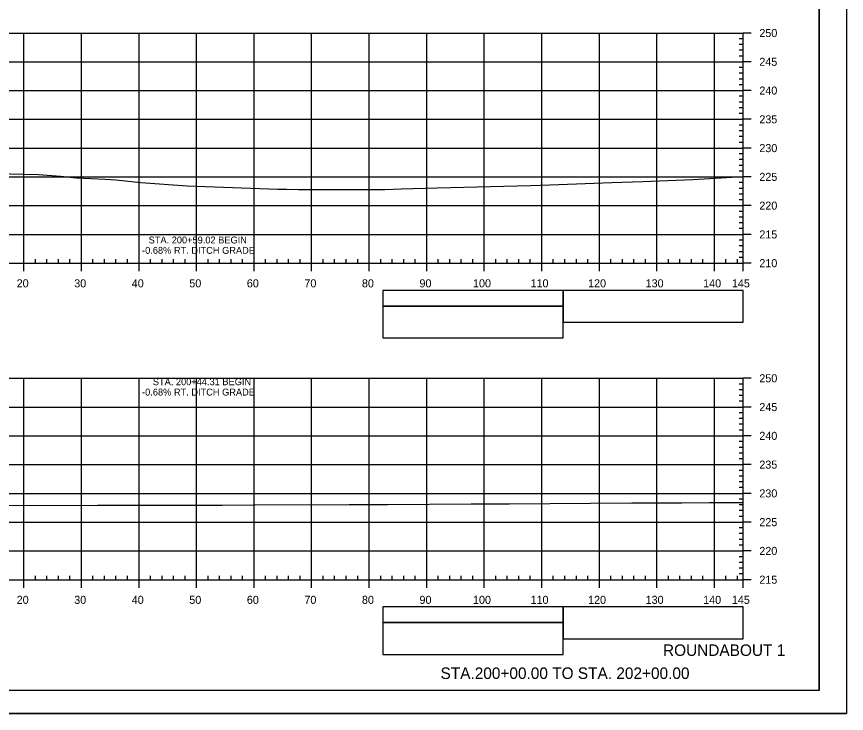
# Model space of a CAD drawing. Extents: x 1386544 to 1388153, y 379785 to 390999.
# Drawn here: x 1387399.1 to 1387543.3, y 380478.3 to 380599.4 of the extents above; entities that cross this region are included whole.
import ezdxf

# ---------------------------------------------------------------- set-up
doc = ezdxf.new("R2010")
doc.units = 0
for name, color, linetype in [('R_Axis', 7, 'Continuous'), ('R_Axis Annot', 7, 'Continuous'), ('R_Border', 7, 'Continuous'), ('R_Draft', 7, 'Continuous'), ('R_Exist Surface', 7, 'Continuous'), ('R_Fin Surface', 7, 'Continuous'), ('R_Grid', 7, 'Continuous'), ('R_No Plot', 7, 'Continuous'), ('R_Striping', 7, 'Continuous'), ('R_Xsect Elev', 7, 'Continuous')]:
    doc.layers.add(name, color=color, linetype=linetype)

msp = doc.modelspace()

# ---------------------------------------------------------------- linework, layer by layer
at = {"layer": 'R_Axis'}
for p, q in [((1387525.41, 380595.56), (1387524.71, 380595.56)), ((1387525.41, 380556.56), (1387525.41, 380596.56)), ((1387526.81, 380596.56), (1387525.41, 380596.56)), ((1387525.41, 380594.56), (1387524.71, 380594.56)), ((1387525.41, 380593.56), (1387524.71, 380593.56)), ((1387525.41, 380592.56), (1387524.71, 380592.56)), ((1387526.81, 380591.56), (1387525.41, 380591.56)), ((1387525.41, 380590.56), (1387524.71, 380590.56)), ((1387525.41, 380589.56), (1387524.71, 380589.56)), ((1387525.41, 380588.56), (1387524.71, 380588.56)), ((1387525.41, 380587.56), (1387524.71, 380587.56)), ((1387526.81, 380586.56), (1387525.41, 380586.56)), ((1387525.41, 380585.56), (1387524.71, 380585.56)), ((1387525.41, 380584.56), (1387524.71, 380584.56)), ((1387525.41, 380583.56), (1387524.71, 380583.56)), ((1387525.41, 380582.56), (1387524.71, 380582.56)), ((1387526.81, 380581.56), (1387525.41, 380581.56)), ((1387525.41, 380580.56), (1387524.71, 380580.56)), ((1387525.41, 380579.56), (1387524.71, 380579.56)), ((1387525.41, 380578.56), (1387524.71, 380578.56)), ((1387525.41, 380577.56), (1387524.71, 380577.56)), ((1387526.81, 380576.56), (1387525.41, 380576.56)), ((1387525.41, 380575.56), (1387524.71, 380575.56)), ((1387525.41, 380574.56), (1387524.71, 380574.56)), ((1387525.41, 380573.56), (1387524.71, 380573.56)), ((1387525.41, 380572.56), (1387524.71, 380572.56)), ((1387526.81, 380571.56), (1387525.41, 380571.56)), ((1387525.41, 380570.56), (1387524.71, 380570.56)), ((1387525.41, 380569.56), (1387524.71, 380569.56)), ((1387525.41, 380568.56), (1387524.71, 380568.56)), ((1387525.41, 380567.56), (1387524.71, 380567.56)), ((1387526.81, 380566.56), (1387525.41, 380566.56)), ((1387525.41, 380565.56), (1387524.71, 380565.56)), ((1387525.41, 380564.56), (1387524.71, 380564.56)), ((1387525.41, 380563.56), (1387524.71, 380563.56)), ((1387525.41, 380562.56), (1387524.71, 380562.56)), ((1387525.41, 380560.56), (1387524.71, 380560.56)), ((1387526.81, 380561.56), (1387525.41, 380561.56)), ((1387525.41, 380559.56), (1387524.71, 380559.56)), ((1387525.41, 380558.56), (1387524.71, 380558.56)), ((1387235.41, 380556.56), (1387525.41, 380556.56)), ((1387400.41, 380555.16), (1387400.41, 380556.56)), ((1387402.41, 380556.56), (1387402.41, 380557.26)), ((1387404.41, 380556.56), (1387404.41, 380557.26)), ((1387406.41, 380556.56), (1387406.41, 380557.26)), ((1387408.41, 380556.56), (1387408.41, 380557.26)), ((1387410.41, 380555.16), (1387410.41, 380556.56)), ((1387412.41, 380556.56), (1387412.41, 380557.26)), ((1387414.41, 380556.56), (1387414.41, 380557.26)), ((1387416.41, 380556.56), (1387416.41, 380557.26)), ((1387418.41, 380556.56), (1387418.41, 380557.26)), ((1387420.41, 380555.16), (1387420.41, 380556.56)), ((1387422.41, 380556.56), (1387422.41, 380557.26)), ((1387424.41, 380556.56), (1387424.41, 380557.26)), ((1387426.41, 380556.56), (1387426.41, 380557.26)), ((1387428.41, 380556.56), (1387428.41, 380557.26)), ((1387430.41, 380555.16), (1387430.41, 380556.56)), ((1387432.41, 380556.56), (1387432.41, 380557.26)), ((1387434.41, 380556.56), (1387434.41, 380557.26)), ((1387436.41, 380556.56), (1387436.41, 380557.26)), ((1387438.41, 380556.56), (1387438.41, 380557.26)), ((1387440.41, 380555.16), (1387440.41, 380556.56)), ((1387442.41, 380556.56), (1387442.41, 380557.26)), ((1387444.41, 380556.56), (1387444.41, 380557.26)), ((1387446.41, 380556.56), (1387446.41, 380557.26)), ((1387448.41, 380556.56), (1387448.41, 380557.26)), ((1387450.41, 380555.16), (1387450.41, 380556.56)), ((1387452.41, 380556.56), (1387452.41, 380557.26)), ((1387454.41, 380556.56), (1387454.41, 380557.26)), ((1387456.41, 380556.56), (1387456.41, 380557.26)), ((1387458.41, 380556.56), (1387458.41, 380557.26)), ((1387460.41, 380555.16), (1387460.41, 380556.56)), ((1387462.41, 380556.56), (1387462.41, 380557.26)), ((1387464.41, 380556.56), (1387464.41, 380557.26)), ((1387466.41, 380556.56), (1387466.41, 380557.26)), ((1387468.41, 380556.56), (1387468.41, 380557.26)), ((1387470.41, 380555.16), (1387470.41, 380556.56)), ((1387472.41, 380556.56), (1387472.41, 380557.26)), ((1387474.41, 380556.56), (1387474.41, 380557.26)), ((1387476.41, 380556.56), (1387476.41, 380557.26)), ((1387478.41, 380556.56), (1387478.41, 380557.26)), ((1387480.41, 380555.16), (1387480.41, 380556.56)), ((1387482.41, 380556.56), (1387482.41, 380557.26)), ((1387484.41, 380556.56), (1387484.41, 380557.26)), ((1387486.41, 380556.56), (1387486.41, 380557.26)), ((1387488.41, 380556.56), (1387488.41, 380557.26)), ((1387490.41, 380555.16), (1387490.41, 380556.56)), ((1387492.41, 380556.56), (1387492.41, 380557.26)), ((1387494.41, 380556.56), (1387494.41, 380557.26)), ((1387496.41, 380556.56), (1387496.41, 380557.26)), ((1387498.41, 380556.56), (1387498.41, 380557.26)), ((1387500.41, 380555.16), (1387500.41, 380556.56)), ((1387502.41, 380556.56), (1387502.41, 380557.26)), ((1387504.41, 380556.56), (1387504.41, 380557.26)), ((1387506.41, 380556.56), (1387506.41, 380557.26)), ((1387508.41, 380556.56), (1387508.41, 380557.26)), ((1387510.41, 380555.16), (1387510.41, 380556.56)), ((1387512.41, 380556.56), (1387512.41, 380557.26)), ((1387514.41, 380556.56), (1387514.41, 380557.26)), ((1387516.41, 380556.56), (1387516.41, 380557.26)), ((1387518.41, 380556.56), (1387518.41, 380557.26)), ((1387520.41, 380555.16), (1387520.41, 380556.56)), ((1387522.41, 380556.56), (1387522.41, 380557.26)), ((1387524.41, 380556.56), (1387524.41, 380557.26)), ((1387525.41, 380557.56), (1387524.71, 380557.56)), ((1387525.41, 380555.16), (1387525.41, 380556.56)), ((1387526.81, 380556.56), (1387525.41, 380556.56)), ((1387525.41, 380501.56), (1387525.41, 380536.56)), ((1387526.81, 380536.56), (1387525.41, 380536.56)), ((1387525.41, 380535.56), (1387524.71, 380535.56)), ((1387525.41, 380534.56), (1387524.71, 380534.56)), ((1387525.41, 380533.56), (1387524.71, 380533.56)), ((1387525.41, 380532.56), (1387524.71, 380532.56)), ((1387525.41, 380530.56), (1387524.71, 380530.56)), ((1387526.81, 380531.56), (1387525.41, 380531.56)), ((1387525.41, 380529.56), (1387524.71, 380529.56)), ((1387525.41, 380528.56), (1387524.71, 380528.56)), ((1387525.41, 380527.56), (1387524.71, 380527.56)), ((1387526.81, 380526.56), (1387525.41, 380526.56)), ((1387525.41, 380525.56), (1387524.71, 380525.56)), ((1387525.41, 380524.56), (1387524.71, 380524.56)), ((1387525.41, 380523.56), (1387524.71, 380523.56)), ((1387525.41, 380522.56), (1387524.71, 380522.56)), ((1387525.41, 380520.56), (1387524.71, 380520.56)), ((1387526.81, 380521.56), (1387525.41, 380521.56)), ((1387525.41, 380519.56), (1387524.71, 380519.56)), ((1387525.41, 380518.56), (1387524.71, 380518.56)), ((1387525.41, 380517.56), (1387524.71, 380517.56)), ((1387526.81, 380516.56), (1387525.41, 380516.56)), ((1387525.41, 380515.56), (1387524.71, 380515.56)), ((1387525.41, 380514.56), (1387524.71, 380514.56)), ((1387525.41, 380513.56), (1387524.71, 380513.56)), ((1387525.41, 380512.56), (1387524.71, 380512.56)), ((1387526.81, 380511.56), (1387525.41, 380511.56)), ((1387525.41, 380510.56), (1387524.71, 380510.56)), ((1387525.41, 380509.56), (1387524.71, 380509.56)), ((1387525.41, 380508.56), (1387524.71, 380508.56)), ((1387525.41, 380507.56), (1387524.71, 380507.56)), ((1387526.81, 380506.56), (1387525.41, 380506.56)), ((1387525.41, 380505.56), (1387524.71, 380505.56)), ((1387525.41, 380504.56), (1387524.71, 380504.56)), ((1387525.41, 380503.56), (1387524.71, 380503.56)), ((1387235.41, 380501.56), (1387525.41, 380501.56)), ((1387400.41, 380500.16), (1387400.41, 380501.56)), ((1387402.41, 380501.56), (1387402.41, 380502.26)), ((1387404.41, 380501.56), (1387404.41, 380502.26)), ((1387406.41, 380501.56), (1387406.41, 380502.26)), ((1387408.41, 380501.56), (1387408.41, 380502.26)), ((1387410.41, 380500.16), (1387410.41, 380501.56)), ((1387412.41, 380501.56), (1387412.41, 380502.26)), ((1387414.41, 380501.56), (1387414.41, 380502.26)), ((1387416.41, 380501.56), (1387416.41, 380502.26)), ((1387418.41, 380501.56), (1387418.41, 380502.26)), ((1387420.41, 380500.16), (1387420.41, 380501.56)), ((1387422.41, 380501.56), (1387422.41, 380502.26)), ((1387424.41, 380501.56), (1387424.41, 380502.26)), ((1387426.41, 380501.56), (1387426.41, 380502.26)), ((1387428.41, 380501.56), (1387428.41, 380502.26)), ((1387430.41, 380500.16), (1387430.41, 380501.56)), ((1387432.41, 380501.56), (1387432.41, 380502.26)), ((1387434.41, 380501.56), (1387434.41, 380502.26)), ((1387436.41, 380501.56), (1387436.41, 380502.26)), ((1387438.41, 380501.56), (1387438.41, 380502.26)), ((1387440.41, 380500.16), (1387440.41, 380501.56)), ((1387442.41, 380501.56), (1387442.41, 380502.26)), ((1387444.41, 380501.56), (1387444.41, 380502.26)), ((1387446.41, 380501.56), (1387446.41, 380502.26)), ((1387448.41, 380501.56), (1387448.41, 380502.26)), ((1387450.41, 380500.16), (1387450.41, 380501.56)), ((1387452.41, 380501.56), (1387452.41, 380502.26)), ((1387454.41, 380501.56), (1387454.41, 380502.26)), ((1387456.41, 380501.56), (1387456.41, 380502.26)), ((1387458.41, 380501.56), (1387458.41, 380502.26)), ((1387460.41, 380500.16), (1387460.41, 380501.56)), ((1387462.41, 380501.56), (1387462.41, 380502.26)), ((1387464.41, 380501.56), (1387464.41, 380502.26)), ((1387466.41, 380501.56), (1387466.41, 380502.26)), ((1387468.41, 380501.56), (1387468.41, 380502.26)), ((1387470.41, 380500.16), (1387470.41, 380501.56)), ((1387472.41, 380501.56), (1387472.41, 380502.26)), ((1387474.41, 380501.56), (1387474.41, 380502.26)), ((1387476.41, 380501.56), (1387476.41, 380502.26)), ((1387478.41, 380501.56), (1387478.41, 380502.26)), ((1387480.41, 380500.16), (1387480.41, 380501.56)), ((1387482.41, 380501.56), (1387482.41, 380502.26)), ((1387484.41, 380501.56), (1387484.41, 380502.26)), ((1387486.41, 380501.56), (1387486.41, 380502.26)), ((1387488.41, 380501.56), (1387488.41, 380502.26)), ((1387490.41, 380500.16), (1387490.41, 380501.56)), ((1387492.41, 380501.56), (1387492.41, 380502.26)), ((1387494.41, 380501.56), (1387494.41, 380502.26)), ((1387496.41, 380501.56), (1387496.41, 380502.26)), ((1387498.41, 380501.56), (1387498.41, 380502.26)), ((1387500.41, 380500.16), (1387500.41, 380501.56)), ((1387502.41, 380501.56), (1387502.41, 380502.26)), ((1387504.41, 380501.56), (1387504.41, 380502.26)), ((1387506.41, 380501.56), (1387506.41, 380502.26)), ((1387508.41, 380501.56), (1387508.41, 380502.26)), ((1387510.41, 380500.16), (1387510.41, 380501.56)), ((1387512.41, 380501.56), (1387512.41, 380502.26)), ((1387514.41, 380501.56), (1387514.41, 380502.26)), ((1387516.41, 380501.56), (1387516.41, 380502.26)), ((1387518.41, 380501.56), (1387518.41, 380502.26)), ((1387520.41, 380500.16), (1387520.41, 380501.56)), ((1387522.41, 380501.56), (1387522.41, 380502.26)), ((1387524.41, 380501.56), (1387524.41, 380502.26)), ((1387525.41, 380502.56), (1387524.71, 380502.56)), ((1387525.41, 380500.16), (1387525.41, 380501.56)), ((1387526.81, 380501.56), (1387525.41, 380501.56))]:
    msp.add_line(p, q, dxfattribs=at)
at = {"layer": 'R_Border'}
for q in [(1387538.59, 380687.77), (1387222.41, 380482.31)]:
    msp.add_line((1387538.59, 380482.31), q, dxfattribs=at)
at = {"layer": 'R_Exist Surface'}
for points in [[(1387395.46, 380572.17), (1387402.92, 380571.98), (1387406.75, 380571.69), (1387409.54, 380571.4), (1387414.51, 380571.18), (1387416.37, 380571.07), (1387420.75, 380570.56), (1387428.79, 380570.01), (1387444.53, 380569.41), (1387446.04, 380569.4), (1387448.15, 380569.39), (1387463.12, 380569.35), (1387465.95, 380569.46), (1387472.24, 380569.65), (1387488.44, 380570.08), (1387490.15, 380570.13), (1387491.8, 380570.17), (1387502.56, 380570.57), (1387507.96, 380570.76), (1387516.67, 380571.09), (1387525.41, 380571.61)], [(1387397.2, 380514.43), (1387413.17, 380514.49), (1387417.41, 380514.5), (1387434.84, 380514.54), (1387440.51, 380514.56), (1387456.92, 380514.6), (1387463.57, 380514.62), (1387478.16, 380514.73), (1387484.8, 380514.77), (1387498.9, 380514.87), (1387506.03, 380514.91), (1387514.75, 380514.94), (1387519.58, 380514.95), (1387525.41, 380514.97)]]:
    msp.add_lwpolyline(points, dxfattribs=at)
at = {"layer": 'R_Fin Surface'}
for points in [[(1387494.15, 380546.29), (1387525.41, 380546.29), (1387525.41, 380551.82), (1387494.15, 380551.82)], [(1387494.15, 380491.29), (1387525.41, 380491.29), (1387525.41, 380496.82), (1387494.15, 380496.82)]]:
    msp.add_lwpolyline(points, close=True, dxfattribs=at)
at = {"layer": 'R_Grid'}
for p, q in [((1387235.41, 380596.56), (1387525.41, 380596.56)), ((1387400.41, 380556.56), (1387400.41, 380596.56)), ((1387410.41, 380556.56), (1387410.41, 380596.56)), ((1387420.41, 380556.56), (1387420.41, 380596.56)), ((1387430.41, 380556.56), (1387430.41, 380596.56)), ((1387440.41, 380556.56), (1387440.41, 380596.56)), ((1387450.41, 380556.56), (1387450.41, 380596.56)), ((1387460.41, 380556.56), (1387460.41, 380596.56)), ((1387470.41, 380556.56), (1387470.41, 380596.56)), ((1387480.41, 380556.56), (1387480.41, 380596.56)), ((1387490.41, 380556.56), (1387490.41, 380596.56)), ((1387500.41, 380556.56), (1387500.41, 380596.56)), ((1387510.41, 380556.56), (1387510.41, 380596.56)), ((1387520.41, 380556.56), (1387520.41, 380596.56)), ((1387525.41, 380556.56), (1387525.41, 380596.56)), ((1387235.41, 380591.56), (1387525.41, 380591.56)), ((1387235.41, 380586.56), (1387525.41, 380586.56)), ((1387235.41, 380581.56), (1387525.41, 380581.56)), ((1387309.44, 380576.56), (1387525.41, 380576.56)), ((1387235.41, 380571.56), (1387525.41, 380571.56)), ((1387235.41, 380566.56), (1387525.41, 380566.56)), ((1387235.41, 380561.56), (1387525.41, 380561.56)), ((1387235.41, 380556.56), (1387525.41, 380556.56)), ((1387235.41, 380536.56), (1387525.41, 380536.56)), ((1387400.41, 380501.56), (1387400.41, 380536.56)), ((1387410.41, 380501.56), (1387410.41, 380536.56)), ((1387420.41, 380501.56), (1387420.41, 380536.56)), ((1387430.41, 380501.56), (1387430.41, 380536.56)), ((1387440.41, 380501.56), (1387440.41, 380536.56)), ((1387450.41, 380501.56), (1387450.41, 380536.56)), ((1387460.41, 380501.56), (1387460.41, 380536.56)), ((1387470.41, 380501.56), (1387470.41, 380536.56)), ((1387480.41, 380501.56), (1387480.41, 380536.56)), ((1387490.41, 380501.56), (1387490.41, 380536.56)), ((1387500.41, 380501.56), (1387500.41, 380536.56)), ((1387510.41, 380501.56), (1387510.41, 380536.56)), ((1387520.41, 380501.56), (1387520.41, 380536.56)), ((1387525.41, 380501.56), (1387525.41, 380536.56)), ((1387235.41, 380531.56), (1387525.41, 380531.56)), ((1387235.41, 380526.56), (1387525.41, 380526.56)), ((1387235.41, 380521.56), (1387525.41, 380521.56)), ((1387235.41, 380516.56), (1387525.41, 380516.56)), ((1387235.41, 380511.56), (1387525.41, 380511.56)), ((1387235.41, 380506.56), (1387525.41, 380506.56)), ((1387235.41, 380501.56), (1387525.41, 380501.56))]:
    msp.add_line(p, q, dxfattribs=at)
at = {"layer": 'R_No Plot'}
msp.add_line((1387210.01, 380478.33), (1387543.34, 380478.33), dxfattribs=at)
for points in [[(1387210, 380691.66), (1387543.34, 380691.66), (1387543.34, 380478.33), (1387210, 380478.33)], [(1387456.33, 380687.77), (1387475.95, 380687.77), (1387475.95, 380677.89), (1387492.06, 380677.89), (1387515.26, 380677.89), (1387515.26, 380653.56), (1387538.59, 380653.56), (1387538.59, 380482.31), (1387222.41, 380482.31), (1387222.41, 380687.77)]]:
    msp.add_lwpolyline(points, close=True, dxfattribs=at)
at = {"layer": 'R_Striping'}
for points in [[(1387462.81, 380549.12), (1387494.15, 380549.12), (1387494.15, 380551.82), (1387462.81, 380551.82)], [(1387462.81, 380543.59), (1387494.15, 380543.59), (1387494.15, 380549.12), (1387462.81, 380549.12)], [(1387462.81, 380494.12), (1387494.15, 380494.12), (1387494.15, 380496.82), (1387462.81, 380496.82)], [(1387462.81, 380488.59), (1387494.15, 380488.59), (1387494.15, 380494.12), (1387462.81, 380494.12)]]:
    msp.add_lwpolyline(points, close=True, dxfattribs=at)

# ---------------------------------------------------------------- texts
at = {"layer": 'R_Axis Annot'}
for s, p in [('250', (1387528.21, 380595.86)), ('245', (1387528.21, 380590.86)), ('240', (1387528.21, 380585.86)), ('235', (1387528.21, 380580.86)), ('230', (1387528.21, 380575.86)), ('225', (1387528.21, 380570.86)), ('220', (1387528.21, 380565.86)), ('215', (1387528.21, 380560.86)), ('210', (1387528.21, 380555.86)), ('20', (1387399.15, 380552.36)), ('30', (1387409.15, 380552.36)), ('40', (1387419.15, 380552.36)), ('50', (1387429.15, 380552.36)), ('60', (1387439.15, 380552.36)), ('70', (1387449.15, 380552.36)), ('80', (1387459.15, 380552.36)), ('90', (1387469.15, 380552.36)), ('100', (1387478.45, 380552.36)), ('110', (1387488.45, 380552.36)), ('120', (1387498.45, 380552.36)), ('130', (1387508.45, 380552.36)), ('140', (1387518.45, 380552.36)), ('145', (1387523.44, 380552.36)), ('250', (1387528.21, 380535.86)), ('245', (1387528.21, 380530.86)), ('240', (1387528.21, 380525.86)), ('235', (1387528.21, 380520.86)), ('230', (1387528.21, 380515.86)), ('225', (1387528.21, 380510.86)), ('220', (1387528.21, 380505.86)), ('215', (1387528.21, 380500.86)), ('20', (1387399.15, 380497.36)), ('30', (1387409.15, 380497.36)), ('40', (1387419.15, 380497.36)), ('50', (1387429.15, 380497.36)), ('60', (1387439.15, 380497.36)), ('70', (1387449.15, 380497.36)), ('80', (1387459.15, 380497.36)), ('90', (1387469.15, 380497.36)), ('100', (1387478.45, 380497.36)), ('110', (1387488.45, 380497.36)), ('120', (1387498.45, 380497.36)), ('130', (1387508.45, 380497.36)), ('140', (1387518.45, 380497.36)), ('145', (1387523.44, 380497.36))]:
    msp.add_text(s, height=1.4, dxfattribs=at).set_placement(p)
at = {"layer": 'R_Draft'}
for s, p in [('ROUNDABOUT 1', (1387511.47, 380488.31)), ('STA.200+00.00 TO STA. 202+00.00', (1387472.81, 380484.31))]:
    msp.add_text(s, height=2, dxfattribs=at).set_placement(p)
at = {"layer": 'R_Xsect Elev'}
for s, p in [('STA. 200+59.02 BEGIN ', (1387422.08, 380559.99)), ('-0.68% RT. DITCH GRADE ', (1387420.94, 380558.19)), ('STA. 200+44.31 BEGIN ', (1387422.81, 380535.36)), ('-0.68% RT. DITCH GRADE ', (1387420.94, 380533.56))]:
    msp.add_text(s, height=1.2, dxfattribs=at).set_placement(p)

doc.saveas('drawing.dxf')
